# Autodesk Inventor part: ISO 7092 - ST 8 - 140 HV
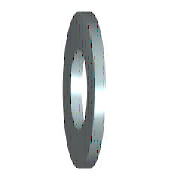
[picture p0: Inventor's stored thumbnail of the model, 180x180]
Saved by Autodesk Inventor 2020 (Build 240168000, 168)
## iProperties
Created: 2019-01
Part Number: ISO 7092 - ST 8 - 140 HV
Material: Acier inoxydable
Description: Rondelle plates - Série petites dimensions - Produit de classe A
Document SubType Name: Modeling
Standard: ISO 7092
Designer: %USERNAME%
Standard Revision: Second edition 2000-06-01
Standards Organization: ISO
Language: fr-FR
Size Designation: ST 8 - 140 HV
Categories: <MemberInstance><Categories><Category DisplayName="Visserie" InternalName="e4da775c-781d-43d5-af7c-5136215cf5a6" Mnemonic="FSTN"><Category DisplayName="Rondelle
Density: 8 g/cm^3
Appearance: Semi-poli
IsCustomPart: 0
Author: %USERNAME%
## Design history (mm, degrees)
body "Solid1"
sketch "Esquisse"
  geometry: C1 r 7.5 at (0, 0); C2 r 4.2 at (0, 0); 1 further point
  constraints: 2 centre point, 2 coincident
  dimensions: "d0" = 8.4 diameter of C2 (= SD1); "d1" = 15 diameter of C1 (= SD2)
extrude "Corps" new body sketch "Esquisse" distance "d2" = 1.6 (= SD); taper "d3" = 0 deg
workaxis "Work Axis1"
workplane "Work Plane1"
other parameters: "SD1" = 8.4 [user parameter; used in 1 equation term], "SD2" = 15 [user parameter; used in 1 equation term], "SD" = 1.6 [user parameter; used in 1 equation term], "d4" = 0, "d5" = 0, "d6" = 0, "d7" = 0, "NND" = 8 [user parameter]
